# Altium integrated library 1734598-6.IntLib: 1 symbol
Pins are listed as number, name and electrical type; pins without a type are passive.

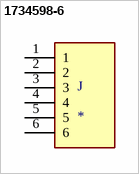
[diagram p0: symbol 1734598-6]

## 1734598-6
designator J
1.25 WTB HDR DIP, 6 POS; Number_of_Positions: 6; MF: TE Connectivity; Product_Type: Connector; Centerline_Pitch: 1.25 mm[.049 in]; MP: 1734598-6
footprint TE_1734598-6
pins: 1, 2, 3, 4, 5, 6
